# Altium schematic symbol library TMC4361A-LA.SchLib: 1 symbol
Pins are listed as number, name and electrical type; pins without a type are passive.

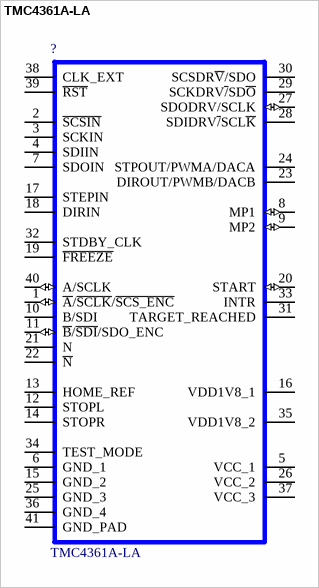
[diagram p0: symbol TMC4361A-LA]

## TMC4361A-LA
designator ?
S-ramp motion controller for stepper motors with high velocities. With SPI and Step/Dir; QFN40(5x5); Manufacturer: TRINAMIC; Geometry.Height: 0.9mm
footprint TMC_QFN40_0.5_6.0X6.0
pins: 1 ~{A}/~{SCLK}/~{SCS_ENC} (io), 2 ~{SCSIN}, 3 SCKIN, 4 SDIIN, 5 VCC_1 (power), 6 GND_1, 7 SDOIN, 8 MP1 (io), 9 MP2 (io), 10 B/SDI, 11 ~{B}/~{SDI}/SDO_ENC (io), 12 STOPL, 13 HOME_REF, 14 STOPR, 15 GND_2, 16 VDD1V8_1 (power), 17 STEPIN, 18 DIRIN, 19 ~{FREEZE}, 20 START (io), 21 N, 22 ~{N}, 23 DIROUT/PWMB/DACB, 24 STPOUT/PWMA/DACA, 25 GND_3, 26 VCC_2 (power), 27 SDODRV/SCLK (io), 28 SDIDRV~{/}SCL~{K}, 29 SCKDRV~{/}SD~{O}, 30 SCSDR~{V}/SDO, 31 TARGET_REACHED, 32 STDBY_CLK, 33 INTR, 34 TEST_MODE, 35 VDD1V8_2 (power), 36 GND_4, 37 VCC_3 (power), 38 CLK_EXT, 39 ~{RST}, 40 A/SCLK (io), 41 GND_PAD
